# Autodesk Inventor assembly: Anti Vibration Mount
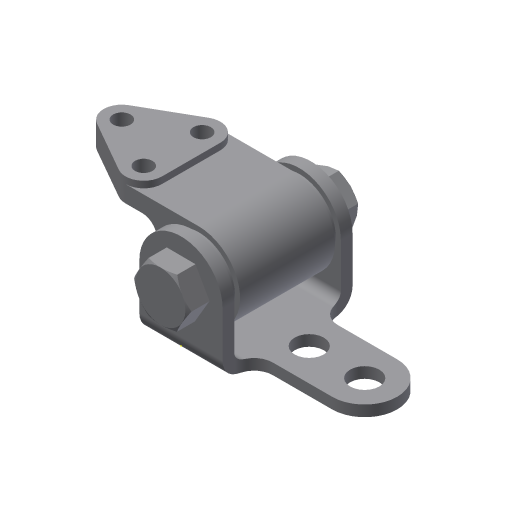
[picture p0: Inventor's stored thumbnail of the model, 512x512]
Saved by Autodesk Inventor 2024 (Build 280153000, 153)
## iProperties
Created: 2011-07
Part Number: Anti Vibration Mount
Document SubType Name: Assembly
Designer: CadCim
Author: CadCim
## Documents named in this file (5)
- D:\PROJECTS\Project 2023\RESOURCES INVENTOR 2024\RESOURCES INVENTOR 2024\Inventor_2024_tut\Inventor_2024_tut\c09_Inv_2024_tut\c09_Inv_2024_tut\c09_Inv_tut_2024\c09_tut03_inv\Anti Vibration Mount\Anti Vibration Mount.iam
- D:\PROJECTS\Project 2023\RESOURCES INVENTOR 2024\RESOURCES INVENTOR 2024\Inventor_2024_tut\Inventor_2024_tut\c09_Inv_2024_tut\c09_Inv_2024_tut\c09_Inv_tut_2024\c09_tut03_inv\Anti Vibration Mount\Yoke Plate.ipt
- D:\PROJECTS\Project 2023\RESOURCES INVENTOR 2024\RESOURCES INVENTOR 2024\Inventor_2024_tut\Inventor_2024_tut\c09_Inv_2024_tut\c09_Inv_2024_tut\c09_Inv_tut_2024\c09_tut03_inv\Anti Vibration Mount\Body-Bushing Ruber.iam
- D:\PROJECTS\Project 2023\RESOURCES INVENTOR 2024\RESOURCES INVENTOR 2024\Inventor_2024_tut\Inventor_2024_tut\c09_Inv_2024_tut\c09_Inv_2024_tut\c09_Inv_tut_2024\c09_tut03_inv\Anti Vibration Mount\Hex Bolt.ipt
- D:\PROJECTS\Project 2023\RESOURCES INVENTOR 2024\RESOURCES INVENTOR 2024\Inventor_2024_tut\Inventor_2024_tut\c09_Inv_2024_tut\c09_Inv_2024_tut\c09_Inv_tut_2024\c09_tut03_inv\Anti Vibration Mount\Nut.ipt
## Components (4 placed, 4 different names)
1. Yoke Plate:1 — Insert:1, Angle:1, Mate:1, Mate:2, Mate:3
2. Body-Bushing Ruber:1 [sub-assembly] — Insert:1, Angle:1
3. Hex Bolt:1 — Mate:2, Mate:3, Mate:4
4. Nut:1 — Mate:1, Mate:4
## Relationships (6: Mate 4, Insert 1, Angle 1)
- Insert:1: Yoke Plate:1 ↔ Body-Bushing Ruber:1
- Angle:1: Yoke Plate:1 ↔ Body-Bushing Ruber:1
- Mate:1: Yoke Plate:1 ↔ Nut:1
- Mate:2: Yoke Plate:1 ↔ Hex Bolt:1
- Mate:3: Yoke Plate:1 ↔ Hex Bolt:1
- Mate:4: Hex Bolt:1 ↔ Nut:1
